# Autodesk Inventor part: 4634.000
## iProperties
Author: kent
Shininess: 29.0
PropertySet Name: _Private Model Information
Created: 2001-06
Part Number: 4634.000
Document SubType Name: Modeling
Designer: kent
Description: Flat Cable Panel Mount Plug
Vendor: 3M
Control State: 0
Master: False
Checked Out: False
PropertySet Name: Design Tracking Control
Density: 0.0
Volumn: 0.0
Area: 0.0
PropertySet Name: Model Information
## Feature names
1. Extrusion1
2. Extrusion2
3. Extrusion3
4. Extrusion4
5. Extrusion5
6. Hole1
7. Extrusion6
8. Extrusion7
9. Extrusion8
10. Rectangular Pattern1
